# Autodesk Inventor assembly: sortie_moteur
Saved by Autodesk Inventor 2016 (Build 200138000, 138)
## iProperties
Created: 2013-08
Part Number: sortie_moteur
Document SubType Name: Assembly
Designer: hilarion
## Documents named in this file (3)
- S:\TSTI2D\Documents en consultation\etude de cas 1  webcam\Webcam motorisee\sortie_moteur.iam
- S:\TSTI2D\Documents en consultation\etude de cas 1  webcam\Webcam motorisee\Roue dentée Moteur.ipt
- S:\TSTI2D\Documents en consultation\etude de cas 1  webcam\Webcam motorisee\axe_sortie_moteur.ipt
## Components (2 placed, 2 different names)
1. Roue dentée Moteur:1
2. axe_sortie_moteur:1
